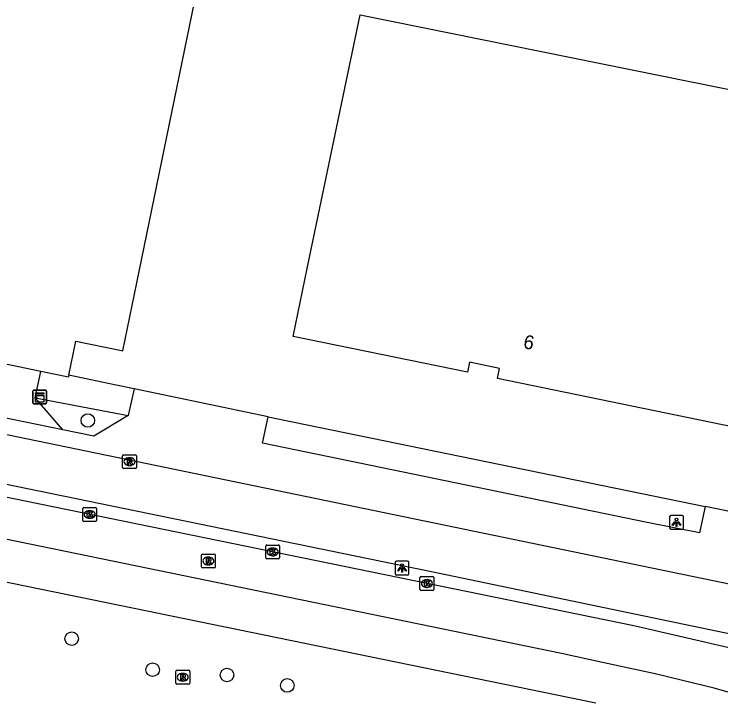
# Model space of a CAD drawing. Extents: x 157692 to 159670, y 381454 to 383289.
# Drawn here: x 158729.2 to 158780.2, y 382073.3 to 382122.5 of the extents above; entities that cross this region are included whole.
import ezdxf

# ---------------------------------------------------------------- set-up
doc = ezdxf.new("R2010")
doc.units = 0
for name, color, linetype in [('IMGEO_Boom', 7, 'Continuous'), ('IMGEO_Erf', 7, 'Continuous'), ('IMGEO_Fietspad_gesloten', 7, 'Continuous'), ('IMGEO_Kast', 7, 'Continuous'), ('IMGEO_Kolk', 7, 'Continuous'), ('IMGEO_Lichtpunt', 7, 'Continuous'), ('IMGEO_Pand', 7, 'Continuous'), ('IMGEO_Pand_nummerreeks', 7, 'Continuous'), ('IMGEO_Rijbaan_lokaal_open', 7, 'Continuous'), ('IMGEO_Rijbaan_regionaal_gesloten', 7, 'Continuous'), ('IMGEO_Rioolput', 7, 'Continuous'), ('IMGEO_Voetpad_open', 7, 'Continuous')]:
    doc.layers.add(name, color=color, linetype=linetype)

msp = doc.modelspace()

# ---------------------------------------------------------------- linework, layer by layer
at = {"layer": 'IMGEO_Boom'}
for centre in [(158734.541, 382093.226), (158733.382, 382077.479), (158739.223, 382075.24), (158744.588, 382074.858), (158748.939, 382074.106)]:
    msp.add_circle(centre, 0.489, dxfattribs=at)
at = {"layer": 'IMGEO_Erf'}
msp.add_lwpolyline([(158733.173, 382096.498), (158733.679, 382098.961), (158736.964, 382098.286), (158737.08, 382098.262), (158738.086, 382103.16), (158746.409, 382143.691)], dxfattribs=at)
at = {"layer": 'IMGEO_Fietspad_gesloten'}
msp.add_lwpolyline([(158640.458, 382106.746), (158759.226, 382082.344), (158791.317, 382075.663)], dxfattribs=at)
at = {"layer": 'IMGEO_Kast'}
for p, q in [((158730.567, 382094.495), (158730.567, 382095.336)), ((158730.567, 382095.336), (158730.567, 382094.495)), ((158730.642, 382095.42), (158731.483, 382095.42)), ((158731.483, 382095.42), (158730.642, 382095.42)), ((158731.567, 382095.345), (158731.567, 382094.504)), ((158731.567, 382094.504), (158731.567, 382095.345)), ((158731.492, 382094.42), (158730.651, 382094.42)), ((158730.651, 382094.42), (158731.492, 382094.42))]:
    msp.add_line(p, q, dxfattribs=at)
for points in [[(158730.762, 382095.21), (158731.362, 382095.21), (158731.362, 382095.125), (158730.762, 382095.125), (158730.762, 382095.21)], [(158730.762, 382095.035), (158731.362, 382095.035), (158731.362, 382094.546), (158730.762, 382094.546), (158730.762, 382095.035)]]:
    msp.add_lwpolyline(points, dxfattribs=at)
msp.add_circle((158730.846, 382094.884), 0.0377, dxfattribs=at)
for centre, start, end in [((158730.645, 382095.342), 92.4484, 184.2845), ((158730.645, 382095.342), 92.4484, 184.2845), ((158731.489, 382095.342), 2.4484, 94.2845), ((158731.489, 382095.342), 2.4484, 94.2845), ((158730.645, 382094.498), 182.4484, 274.2845), ((158730.645, 382094.498), 182.4484, 274.2845), ((158731.489, 382094.498), 272.4484, 4.2845), ((158731.489, 382094.498), 272.4484, 4.2845)]:
    msp.add_arc(centre, 0.0779, start, end, dxfattribs=at)
at = {"layer": 'IMGEO_Kolk'}
for p, q in [((158734.173, 382086.02), (158734.173, 382086.872)), ((158734.248, 382086.946), (158735.1, 382086.946)), ((158734.661, 382086.726), (158734.686, 382086.726)), ((158735.174, 382086.872), (158735.174, 382086.02)), ((158734.684, 382086.166), (158734.659, 382086.166)), ((158735.1, 382085.946), (158734.248, 382085.946)), ((158747.386, 382083.314), (158747.386, 382084.166)), ((158747.461, 382084.24), (158748.313, 382084.24)), ((158747.874, 382084.02), (158747.899, 382084.02)), ((158748.387, 382084.166), (158748.387, 382083.314)), ((158747.897, 382083.46), (158747.872, 382083.46)), ((158748.313, 382083.24), (158747.461, 382083.24)), ((158758.519, 382081.033), (158758.519, 382081.885)), ((158758.594, 382081.959), (158759.446, 382081.959)), ((158759.52, 382081.885), (158759.52, 382081.033)), ((158759.007, 382081.739), (158759.032, 382081.739)), ((158759.446, 382080.959), (158758.594, 382080.959)), ((158759.03, 382081.179), (158759.005, 382081.179))]:
    msp.add_line(p, q, dxfattribs=at)
for points in [[(158734.173, 382086.02), (158734.173, 382086.872)], [(158734.248, 382086.946), (158735.1, 382086.946)], [(158734.494, 382086.646), (158734.617, 382086.646), (158734.617, 382086.495), (158734.747, 382086.646), (158734.911, 382086.646), (158734.765, 382086.495), (158734.918, 382086.246), (158734.766, 382086.246), (158734.681, 382086.41), (158734.617, 382086.343), (158734.617, 382086.246), (158734.494, 382086.246), (158734.494, 382086.646)], [(158735.174, 382086.872), (158735.174, 382086.02)], [(158735.1, 382085.946), (158734.248, 382085.946)], [(158747.386, 382083.314), (158747.386, 382084.166)], [(158747.461, 382084.24), (158748.313, 382084.24)], [(158747.707, 382083.94), (158747.83, 382083.94), (158747.83, 382083.789), (158747.96, 382083.94), (158748.124, 382083.94), (158747.978, 382083.789), (158748.131, 382083.54), (158747.979, 382083.54), (158747.894, 382083.704), (158747.83, 382083.637), (158747.83, 382083.54), (158747.707, 382083.54), (158747.707, 382083.94)], [(158748.387, 382084.166), (158748.387, 382083.314)], [(158748.313, 382083.24), (158747.461, 382083.24)], [(158758.519, 382081.033), (158758.519, 382081.885)], [(158758.594, 382081.959), (158759.446, 382081.959)], [(158759.52, 382081.885), (158759.52, 382081.033)], [(158758.84, 382081.659), (158758.963, 382081.659), (158758.963, 382081.508), (158759.093, 382081.659), (158759.257, 382081.659), (158759.111, 382081.508), (158759.264, 382081.259), (158759.112, 382081.259), (158759.027, 382081.423), (158758.963, 382081.356), (158758.963, 382081.259), (158758.84, 382081.259), (158758.84, 382081.659)], [(158759.446, 382080.959), (158758.594, 382080.959)]]:
    msp.add_lwpolyline(points, dxfattribs=at)
for centre, start, end in [((158734.25, 382086.87), 91.552, 178.448), ((158734.25, 382086.87), 91.552, 178.448), ((158735.098, 382086.87), 1.552, 88.448), ((158735.098, 382086.87), 1.552, 88.448), ((158734.25, 382086.022), 181.552, 268.448), ((158734.25, 382086.022), 181.552, 268.448), ((158735.098, 382086.022), 271.552, 358.448), ((158735.098, 382086.022), 271.552, 358.448), ((158747.463, 382084.164), 91.552, 178.448), ((158747.463, 382084.164), 91.552, 178.448), ((158748.311, 382084.164), 1.552, 88.448), ((158748.311, 382084.164), 1.552, 88.448), ((158747.463, 382083.316), 181.552, 268.448), ((158747.463, 382083.316), 181.552, 268.448), ((158748.311, 382083.316), 271.552, 358.448), ((158748.311, 382083.316), 271.552, 358.448), ((158758.596, 382081.883), 91.552, 178.448), ((158758.596, 382081.883), 91.552, 178.448), ((158759.444, 382081.883), 1.552, 88.448), ((158759.444, 382081.883), 1.552, 88.448), ((158758.596, 382081.035), 181.552, 268.448), ((158758.596, 382081.035), 181.552, 268.448), ((158759.444, 382081.035), 271.552, 358.448), ((158759.444, 382081.035), 271.552, 358.448)]:
    msp.add_arc(centre, 0.0765, start, end, dxfattribs=at)
for centre, major_axis, ratio, start_param, end_param in [((158734.66, 382086.446), (-0.387, 0.002), 0.722429, 4.712389, 7.853982), ((158734.685, 382086.446), (-0.39, 0.002), 0.717154, 1.570796, 4.712389), ((158747.873, 382083.74), (-0.387, 0.002), 0.722429, 4.712389, 7.853982), ((158747.898, 382083.74), (-0.39, 0.002), 0.717154, 1.570796, 4.712389), ((158759.006, 382081.459), (-0.387, 0.002), 0.722429, 4.712389, 7.853982), ((158759.031, 382081.459), (-0.39, 0.002), 0.717154, 1.570796, 4.712389)]:
    msp.add_ellipse(centre, major_axis=major_axis, ratio=ratio, start_param=start_param, end_param=end_param, dxfattribs=at)
at = {"layer": 'IMGEO_Lichtpunt'}
for p, q in [((158776.539, 382086.276), (158776.539, 382085.469)), ((158776.539, 382086.276), (158776.539, 382085.469)), ((158777.441, 382086.371), (158776.633, 382086.371)), ((158777.441, 382086.371), (158776.633, 382086.371)), ((158777.535, 382085.469), (158777.535, 382086.276)), ((158777.535, 382085.469), (158777.535, 382086.276)), ((158776.633, 382085.375), (158777.441, 382085.375)), ((158776.633, 382085.375), (158777.441, 382085.375)), ((158756.722, 382082.977), (158756.722, 382082.17)), ((158756.722, 382082.977), (158756.722, 382082.17)), ((158757.624, 382083.072), (158756.816, 382083.072)), ((158757.624, 382083.072), (158756.816, 382083.072)), ((158757.718, 382082.17), (158757.718, 382082.977)), ((158757.718, 382082.17), (158757.718, 382082.977)), ((158756.816, 382082.076), (158757.624, 382082.076)), ((158756.816, 382082.076), (158757.624, 382082.076))]:
    msp.add_line(p, q, dxfattribs=at)
for points in [[(158776.913, 382085.94), (158776.952, 382085.912), (158776.764, 382085.65), (158776.726, 382085.677), (158776.913, 382085.94)], [(158777.015, 382085.892), (158777.062, 382085.892), (158777.062, 382085.57), (158777.015, 382085.57), (158777.015, 382085.892)], [(158777.125, 382085.912), (158777.163, 382085.939), (158777.35, 382085.677), (158777.311, 382085.649), (158777.125, 382085.912)], [(158757.096, 382082.641), (158757.135, 382082.613), (158756.947, 382082.351), (158756.909, 382082.378), (158757.096, 382082.641)], [(158757.198, 382082.593), (158757.245, 382082.593), (158757.245, 382082.271), (158757.198, 382082.271), (158757.198, 382082.593)], [(158757.308, 382082.613), (158757.346, 382082.64), (158757.533, 382082.378), (158757.494, 382082.35), (158757.308, 382082.613)]]:
    msp.add_lwpolyline(points, dxfattribs=at)
for centre in [(158777.038, 382086.074), (158757.221, 382082.775)]:
    msp.add_circle(centre, 0.0994, dxfattribs=at)
for centre, start, end in [((158776.633, 382086.276), 90, 180), ((158776.633, 382086.276), 90, 180), ((158777.441, 382086.276), 0, 90), ((158777.441, 382086.276), 0, 90), ((158776.633, 382085.469), 180, 270), ((158776.633, 382085.469), 180, 270), ((158777.441, 382085.469), 270, 0), ((158777.441, 382085.469), 270, 360), ((158756.816, 382082.977), 90, 180), ((158756.816, 382082.977), 90, 180), ((158757.624, 382082.977), 0, 90), ((158757.624, 382082.977), 0, 90), ((158756.816, 382082.17), 180, 270), ((158756.816, 382082.17), 180, 270), ((158757.624, 382082.17), 270, 0), ((158757.624, 382082.17), 270, 360)]:
    msp.add_arc(centre, 0.0946, start, end, dxfattribs=at)
at = {"layer": 'IMGEO_Pand'}
msp.add_lwpolyline([(158786.796, 382115.911), (158783.008, 382097.477), (158782.001, 382092.579), (158764.114, 382096.257), (158764.263, 382096.981), (158762.098, 382097.428), (158761.948, 382096.702), (158749.361, 382099.29), (158750.384, 382104.185), (158754.21, 382122.499), (158786.796, 382115.911)], dxfattribs=at)
at = {"layer": 'IMGEO_Rijbaan_lokaal_open'}
for points in [[(158620.94, 382114.323), (158712.956, 382095.452), (158809.708, 382075.476)], [(158731.142, 382096.767), (158725.714, 382097.882)], [(158730.749, 382094.853), (158731.142, 382096.767)], [(158737.882, 382095.512), (158737.459, 382093.585)], [(158747.563, 382093.491), (158737.882, 382095.512)], [(158732.747, 382092.544), (158730.749, 382094.853)], [(158732.747, 382092.544), (158723.335, 382094.483)], [(158737.459, 382093.585), (158734.967, 382092.09), (158732.747, 382092.544)], [(158779.094, 382087.008), (158778.693, 382085.11), (158774.926, 382085.873), (158751.126, 382090.777), (158747.156, 382091.589), (158747.563, 382093.491)], [(158828.413, 382068.102), (158829.393, 382072.876), (158854.168, 382067.855), (158855.441, 382074.005), (158832.164, 382078.78), (158831.712, 382076.46), (158814.541, 382079.95), (158814.452, 382079.413), (158811.515, 382080.009), (158811.125, 382080.406), (158785.901, 382085.615), (158779.094, 382087.008)]]:
    msp.add_lwpolyline(points, dxfattribs=at)
at = {"layer": 'IMGEO_Rijbaan_regionaal_gesloten'}
for points in [[(158790.901, 382074.003), (158788.955, 382074.588), (158781.033, 382076.781), (158773.962, 382078.399), (158640.25, 382105.785)], [(158812.129, 382060.118), (158798.29, 382067.268), (158793.04, 382069.515), (158792.18, 382069.883), (158791.247, 382070.227), (158790.426, 382070.553), (158789.016, 382071.05), (158788.126, 382071.378), (158787.681, 382071.52), (158784.175, 382072.638), (158779.753, 382073.898), (158778.255, 382074.275), (158775.501, 382074.941), (158771.698, 382075.766), (158768.722, 382076.412), (158725.181, 382085.35), (158678.367, 382094.92), (158638.613, 382103.052)], [(158638.357, 382100.078), (158771.214, 382072.861)]]:
    msp.add_lwpolyline(points, dxfattribs=at)
at = {"layer": 'IMGEO_Rioolput'}
for p, q in [((158737.051, 382089.831), (158737.051, 382090.683)), ((158737.126, 382090.757), (158737.978, 382090.757)), ((158738.052, 382090.683), (158738.052, 382089.831)), ((158737.539, 382090.537), (158737.564, 382090.537)), ((158737.978, 382089.757), (158737.126, 382089.757)), ((158737.562, 382089.977), (158737.537, 382089.977)), ((158742.745, 382082.659), (158742.745, 382083.511)), ((158742.82, 382083.585), (158743.672, 382083.585)), ((158743.746, 382083.511), (158743.746, 382082.659)), ((158743.233, 382083.365), (158743.258, 382083.365)), ((158743.672, 382082.585), (158742.82, 382082.585)), ((158743.256, 382082.805), (158743.231, 382082.805)), ((158740.893, 382074.271), (158740.893, 382075.123)), ((158740.968, 382075.197), (158741.82, 382075.197)), ((158741.381, 382074.977), (158741.406, 382074.977)), ((158741.894, 382075.123), (158741.894, 382074.271)), ((158741.404, 382074.417), (158741.379, 382074.417)), ((158741.82, 382074.197), (158740.968, 382074.197))]:
    msp.add_line(p, q, dxfattribs=at)
for points in [[(158737.051, 382089.831), (158737.051, 382090.683)], [(158737.126, 382090.757), (158737.978, 382090.757)], [(158738.052, 382090.683), (158738.052, 382089.831)], [(158737.64, 382090.455), (158737.388, 382090.457), (158737.388, 382090.057)], [(158737.388, 382090.057), (158737.512, 382090.057), (158737.512, 382090.219), (158737.523, 382090.219)], [(158737.566, 382090.376), (158737.512, 382090.376), (158737.512, 382090.295)], [(158737.512, 382090.295), (158737.564, 382090.295)], [(158737.57, 382090.19), (158737.641, 382090.057), (158737.781, 382090.057), (158737.716, 382090.183)], [(158737.978, 382089.757), (158737.126, 382089.757)], [(158742.745, 382082.659), (158742.745, 382083.511)], [(158742.82, 382083.585), (158743.672, 382083.585)], [(158743.746, 382083.511), (158743.746, 382082.659)], [(158743.334, 382083.283), (158743.082, 382083.285), (158743.082, 382082.885)], [(158743.082, 382082.885), (158743.206, 382082.885), (158743.206, 382083.047), (158743.217, 382083.047)], [(158743.26, 382083.204), (158743.206, 382083.204), (158743.206, 382083.123)], [(158743.206, 382083.123), (158743.258, 382083.123)], [(158743.264, 382083.018), (158743.335, 382082.885), (158743.475, 382082.885), (158743.41, 382083.011)], [(158743.672, 382082.585), (158742.82, 382082.585)], [(158740.893, 382074.271), (158740.893, 382075.123)], [(158740.968, 382075.197), (158741.82, 382075.197)], [(158741.482, 382074.895), (158741.23, 382074.897), (158741.23, 382074.497)], [(158741.408, 382074.816), (158741.354, 382074.816), (158741.354, 382074.735)], [(158741.354, 382074.735), (158741.406, 382074.735)], [(158741.894, 382075.123), (158741.894, 382074.271)], [(158741.23, 382074.497), (158741.354, 382074.497), (158741.354, 382074.659), (158741.365, 382074.659)], [(158741.412, 382074.63), (158741.483, 382074.497), (158741.623, 382074.497), (158741.558, 382074.623)], [(158741.82, 382074.197), (158740.968, 382074.197)]]:
    msp.add_lwpolyline(points, dxfattribs=at)
for centre, radius, start, end in [((158737.128, 382090.681), 0.0765, 91.552, 178.448), ((158737.128, 382090.681), 0.0765, 91.552, 178.448), ((158737.976, 382090.681), 0.0765, 1.552, 88.448), ((158737.976, 382090.681), 0.0765, 1.552, 88.448), ((158737.522, 382090.166), 0.0533, 26.0293, 88.6989), ((158737.548, 382090.484), 0.19, 274.7715, 282.9687), ((158737.572, 382090.28), 0.0964, 77.0061, 93.1865), ((158737.586, 382090.337), 0.0378, 276.6634, 79.6772), ((158737.639, 382090.345), 0.109, 350.3612, 89.416), ((158737.637, 382090.345), 0.112, 277.5842, 350.9817), ((158737.621, 382090.13), 0.108, 29.5134, 73.7905), ((158737.128, 382089.833), 0.0765, 181.552, 268.448), ((158737.128, 382089.833), 0.0765, 181.552, 268.448), ((158737.976, 382089.833), 0.0765, 271.552, 358.448), ((158737.976, 382089.833), 0.0765, 271.552, 358.448), ((158742.822, 382083.509), 0.0765, 91.552, 178.448), ((158742.822, 382083.509), 0.0765, 91.552, 178.448), ((158743.67, 382083.509), 0.0765, 1.552, 88.448), ((158743.67, 382083.509), 0.0765, 1.552, 88.448), ((158743.216, 382082.994), 0.0533, 26.0293, 88.6989), ((158743.242, 382083.312), 0.19, 274.7715, 282.9687), ((158743.266, 382083.108), 0.0964, 77.0061, 93.1865), ((158743.28, 382083.165), 0.0378, 276.6634, 79.6772), ((158743.333, 382083.173), 0.109, 350.3612, 89.416), ((158743.331, 382083.173), 0.112, 277.5842, 350.9817), ((158743.315, 382082.958), 0.108, 29.5134, 73.7905), ((158742.822, 382082.661), 0.0765, 181.552, 268.448), ((158742.822, 382082.661), 0.0765, 181.552, 268.448), ((158743.67, 382082.661), 0.0765, 271.552, 358.448), ((158743.67, 382082.661), 0.0765, 271.552, 358.448), ((158740.97, 382075.121), 0.0765, 91.552, 178.448), ((158740.97, 382075.121), 0.0765, 91.552, 178.448), ((158741.39, 382074.924), 0.19, 274.7715, 282.9687), ((158741.414, 382074.72), 0.0964, 77.0061, 93.1865), ((158741.428, 382074.777), 0.0378, 276.6634, 79.6772), ((158741.481, 382074.785), 0.109, 350.3612, 89.416), ((158741.479, 382074.785), 0.112, 277.5842, 350.9817), ((158741.818, 382075.121), 0.0765, 1.552, 88.448), ((158741.818, 382075.121), 0.0765, 1.552, 88.448), ((158740.97, 382074.273), 0.0765, 181.552, 268.448), ((158740.97, 382074.273), 0.0765, 181.552, 268.448), ((158741.364, 382074.606), 0.0533, 26.0293, 88.6989), ((158741.463, 382074.57), 0.108, 29.5134, 73.7905), ((158741.818, 382074.273), 0.0765, 271.552, 358.448), ((158741.818, 382074.273), 0.0765, 271.552, 358.448)]:
    msp.add_arc(centre, radius, start, end, dxfattribs=at)
for centre, major_axis, ratio, start_param, end_param in [((158737.538, 382090.257), (-0.387, 0.002), 0.722429, 4.712389, 7.853982), ((158737.563, 382090.257), (-0.39, 0.002), 0.717154, 1.570796, 4.712389), ((158743.232, 382083.085), (-0.387, 0.002), 0.722429, 4.712389, 7.853982), ((158743.257, 382083.085), (-0.39, 0.002), 0.717154, 1.570796, 4.712389), ((158741.38, 382074.697), (-0.387, 0.002), 0.722429, 4.712389, 7.853982), ((158741.405, 382074.697), (-0.39, 0.002), 0.717154, 1.570796, 4.712389)]:
    msp.add_ellipse(centre, major_axis=major_axis, ratio=ratio, start_param=start_param, end_param=end_param, dxfattribs=at)
at = {"layer": 'IMGEO_Voetpad_open'}
for points in [[(158733.173, 382096.498), (158733.144, 382096.356), (158731.142, 382096.767)], [(158737.882, 382095.512), (158736.463, 382095.809), (158733.173, 382096.498)], [(158730.749, 382094.853), (158737.459, 382093.585)], [(158747.563, 382093.491), (158779.094, 382087.008)]]:
    msp.add_lwpolyline(points, dxfattribs=at)

# ---------------------------------------------------------------- texts
at = {"layer": 'IMGEO_Pand_nummerreeks'}
msp.add_text('6', height=1, rotation=348.3815, dxfattribs=at).set_placement((158765.919, 382098.458))

doc.saveas('drawing.dxf')
